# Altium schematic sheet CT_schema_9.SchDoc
size 308 x 210 mm
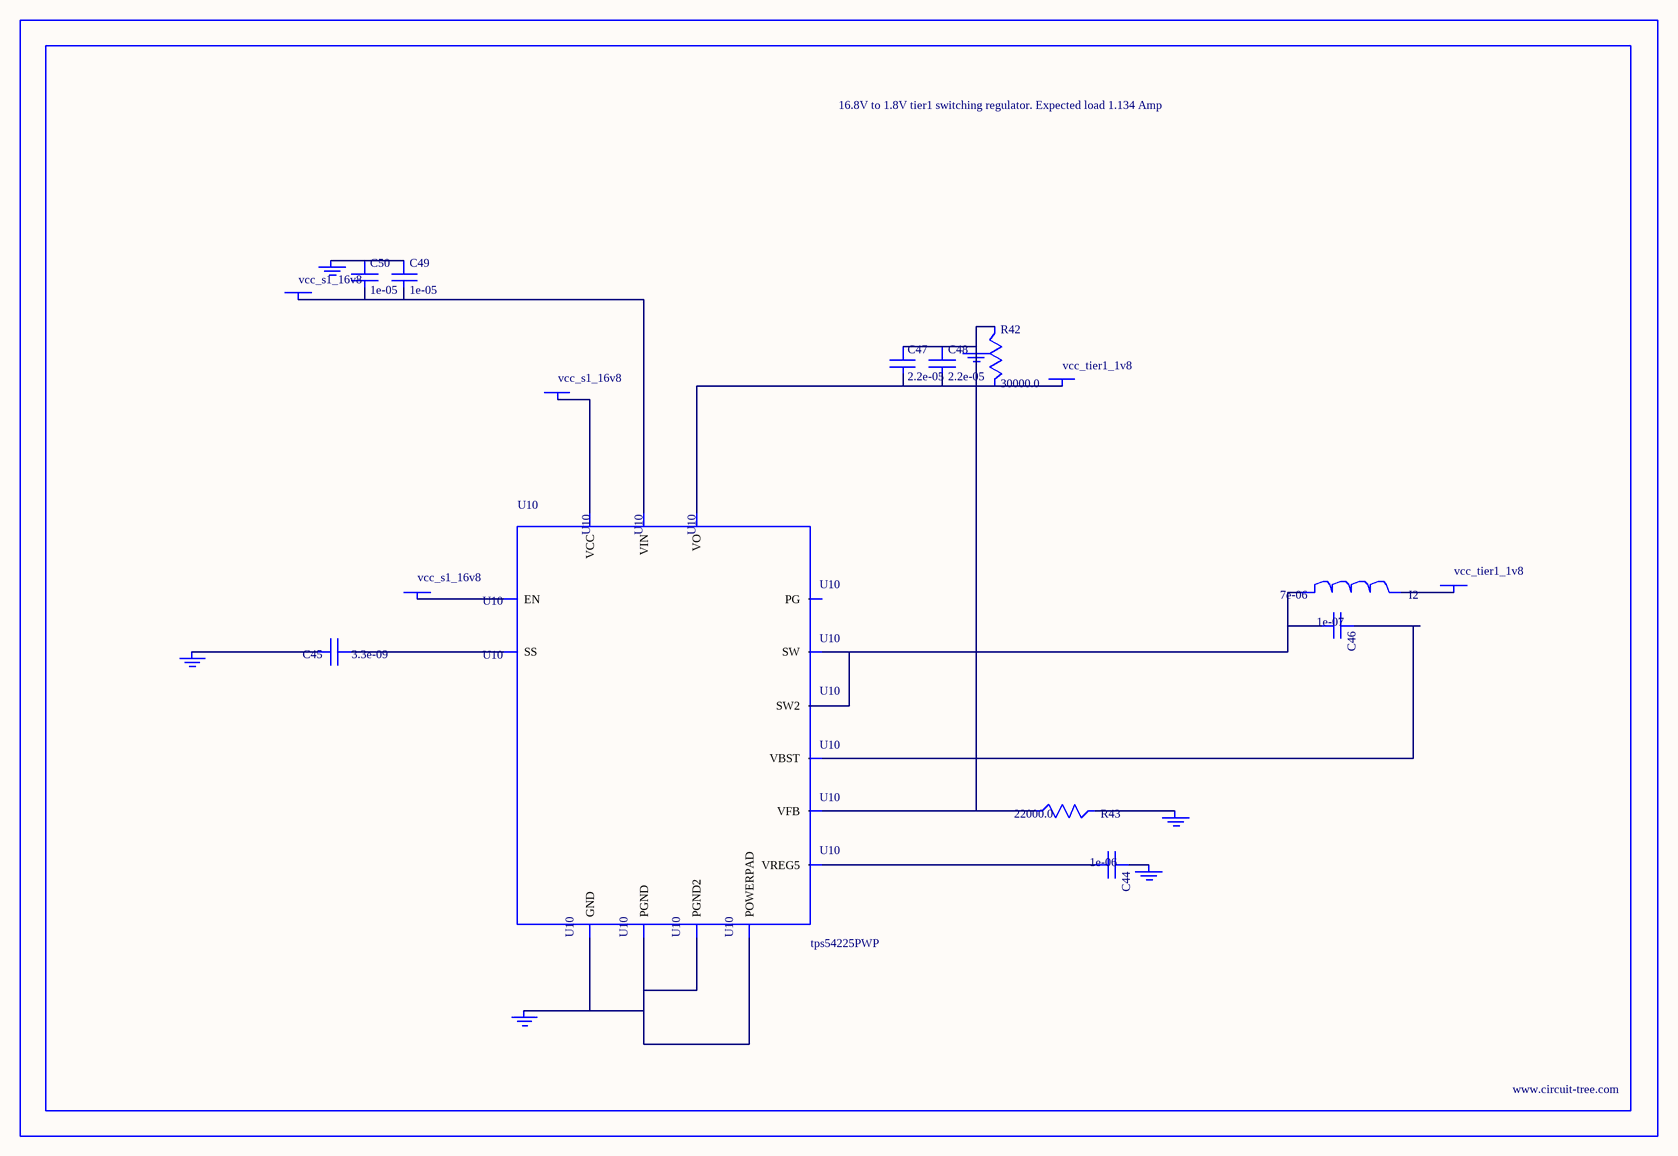
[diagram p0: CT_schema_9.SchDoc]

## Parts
BORDER8  (no value)
C44  1e-06  [C0603]
C45  3.3e-09  [C0402]
C46  1e-07  [C0402]
C47  2.2e-05  [C1210]
C48  2.2e-05  [C1210]
C49  1e-05  [C1210]
C50  1e-05  [C1210]
GND_INSTANCE_8_0  (no value)
GND_INSTANCE_8_1  (no value)
GND_INSTANCE_8_2  (no value)
GND_INSTANCE_8_3  (no value)
GND_INSTANCE_8_4  (no value)
GND_INSTANCE_8_5  (no value)
I2  7e-06  [DR1040]
POWER_INSTANCE_8_0  vcc_tier1_1v8
POWER_INSTANCE_8_1  vcc_s1_16v8
POWER_INSTANCE_8_2  vcc_tier1_1v8
POWER_INSTANCE_8_3  vcc_s1_16v8
POWER_INSTANCE_8_4  vcc_s1_16v8
R42  30000.0  [R0603]
R43  22000.0  [R0603]
U10  tps54225PWP  [HTSSOP14]

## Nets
NetC44_1: C44.1 GND_INSTANCE_8_2.0(GND)
NetC44_2: C44.2 U10.3(VREG5)
NetC45_1: C45.1 U10.4(SS)
NetC45_2: C45.2 GND_INSTANCE_8_3.0(GND)
NetC46_1: C46.1 U10.12(VBST)
NetC46_2: C46.2 I2.1 U10.10(SW) U10.11(SW2)
NetC47_1: C47.1 C48.1 GND_INSTANCE_8_0.0(GND) R42.1 R43.1 U10.2(VFB)
NetC47_2: C47.2 C48.2 POWER_INSTANCE_8_0.0(PWR) R42.2 U10.1(VO)
NetC49_1: C49.1 C50.1 GND_INSTANCE_8_5.0(GND)
NetC49_2: C49.2 C50.2 POWER_INSTANCE_8_3.0(PWR) U10.13(VIN)
NetGND_INSTANCE_8_1_0: GND_INSTANCE_8_1.0(GND) R43.2
NetGND_INSTANCE_8_4_0: GND_INSTANCE_8_4.0(GND) U10.5(GND) U10.8(PGND) U10.9(PGND2) U10.15(POWERPAD)
NetI2_2: I2.2 POWER_INSTANCE_8_2.0(PWR)
NetPOWER_INSTANCE_8_1_0: POWER_INSTANCE_8_1.0(PWR) U10.7(EN)
NetPOWER_INSTANCE_8_4_0: POWER_INSTANCE_8_4.0(PWR) U10.14(VCC)

Not connected (* = marked no-connect by the designer): U10 6(PG)

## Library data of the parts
BORDER8 = BORDER_PAGE8
C44 = C0603C105K3RACTU
C45 = C0402C332K3RAC
C46 = C0402C104K3RACTU
C47 C48 = GRM32ER61E226ME15L
C49 C50 = C1210C106K5PACTU
GND_INSTANCE_8_0-GND_INSTANCE_8_5 = GND
I2 = DR1040-7R0-R
POWER_INSTANCE_8_0-POWER_INSTANCE_8_4 = PWR
R42 = RC0603JR-0730KL
R43 = RC0603JR-0722KL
